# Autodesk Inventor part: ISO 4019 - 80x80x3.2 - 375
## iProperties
Created: 2007-05
Part Number: ISO 4019 - 80x80x3.2 - 375
Material: Steel, Mild
Description: Cold-Finished Hollow Section
Vendor: Autodesk Inc.
Document SubType Name: Modeling
Standard: ISO 4019
Designer: kurs1
Standards Organization: ISO
Language: en-US
Size Designation: 80x80x3.2 - 375
Categories: <MemberInstance Version="R10.0.0"><Categories><Category DisplayName="Steel Shapes" InternalName="089c4875-fa83-4c05-b084-43b9cc11f5ed" Mnemonic="GRDR"><Category
Stock Number: 80x80x3.2
Density: 1 g/cm^3
G_L: 375,000 mm
Author: kurs1
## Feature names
1. Body [Extrusion]
2. Fillet1
3. Fillet2
